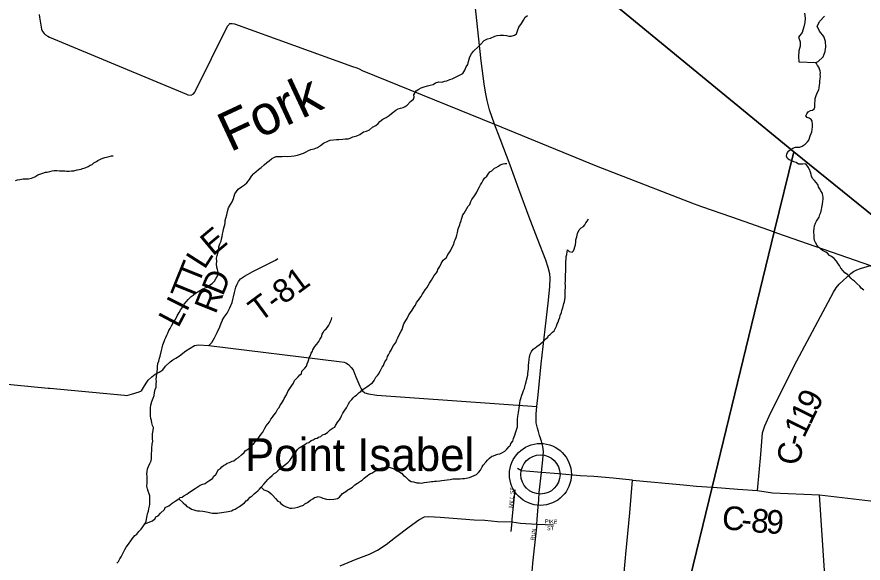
# Model space of a CAD drawing. Extents: x 1310247 to 1664935, y 235267 to 584339.
# Drawn here: x 1497464 to 1508215, y 329459 to 336394 of the extents above; entities that cross this region are included whole.
import ezdxf

# ---------------------------------------------------------------- set-up
doc = ezdxf.new("R2010")
doc.units = 0
for name, color, linetype in [('GM_X_County_Road', 7, 'Continuous'), ('GM_X_County_Road_Text', 7, 'Continuous'), ('GM_X_Minor_Lake', 7, 'Continuous'), ('GM_X_Minor_River', 7, 'Continuous'), ('GM_X_Minor_River_Text', 7, 'Continuous'), ('GM_X_State_Route', 7, 'Continuous'), ('GM_X_Township', 7, 'Continuous'), ('GM_X_Township_Road', 7, 'Continuous'), ('GM_X_Township_Road_Text', 7, 'Continuous'), ('GM_X_Township_ROW', 7, 'Continuous'), ('GM_X_Township_Subdivision', 7, 'Continuous'), ('GM_X_Township_Subdivision_Text', 7, 'Continuous'), ('GM_X_Unincorporated', 7, 'Continuous'), ('GM_X_Unincorporated_Location', 7, 'Continuous'), ('GM_X_Unincorporated_Text', 7, 'Continuous')]:
    doc.layers.add(name, color=color, linetype=linetype)

msp = doc.modelspace()

# ---------------------------------------------------------------- linework, layer by layer
at = {"layer": 'GM_X_County_Road'}
for points in [[(1506874, 330380), (1506915, 330836), (1506931, 331059), (1506937, 331113), (1506950, 331153), (1506966, 331203), (1507040, 331363), (1507375, 332029), (1507838, 332899), (1507873, 332955), (1507912, 332999), (1508061, 333136), (1508091, 333160), (1508134, 333183), (1508184, 333201), (1508308, 333237)], [(1497863, 331681), (1497884, 331679), (1498831, 331590), (1498861, 331589), (1498918, 331604), (1499019, 331633), (1499045, 331647), (1499074, 331690), (1499106, 331745), (1499133, 331781), (1499180, 331826), (1499221, 331857), (1499271, 331882), (1499294, 331897), (1499316, 331911), (1499353, 331958), (1499409, 332013), (1499444, 332040), (1499484, 332063), (1499529, 332092), (1499611, 332154), (1499720, 332221), (1499773, 332232), (1499902, 332221), (1501558, 332017), (1501620, 332010), (1501644, 332003), (1501676, 331980), (1501709, 331943), (1501734, 331911), (1501762, 331846), (1501766, 331837)], [(1506310, 330422), (1506622, 330398), (1506874, 330380), (1507062, 330352), (1507660, 330327), (1508525, 330224), (1508611, 330218), (1508671, 330227), (1508722, 330257), (1508766, 330296), (1508807, 330348), (1508927, 330527), (1509888, 331954), (1509935, 332016), (1509965, 332043), (1509999, 332057), (1510060, 332056), (1510186, 332039), (1510688, 331967), (1510706, 331965)], [(1501766, 331837), (1501770, 331826), (1501794, 331763), (1501819, 331704), (1501836, 331673), (1501855, 331645), (1501885, 331622), (1501930, 331607), (1502036, 331590), (1504071, 331446)], [(1497210, 331743), (1497863, 331681)], [(1505285, 330514), (1505934, 330451), (1506099, 330437), (1506297, 330423), (1506310, 330422)], [(1508425, 324502), (1508196, 324828), (1508120, 324927), (1508065, 325019), (1508047, 325076), (1508014, 325188), (1507987, 325289), (1507959, 325402), (1507847, 325823), (1507823, 325940), (1507813, 326025), (1507811, 326169), (1507819, 326315), (1507833, 326564), (1507841, 326866), (1507838, 327042), (1507841, 327152), (1507849, 327306), (1507850, 327552), (1507836, 327784), (1507790, 328404), (1507660, 330327)]]:
    msp.add_lwpolyline(points, dxfattribs=at)
at = {"layer": 'GM_X_Minor_Lake'}
for points in [[(1507472, 336443), (1507477, 336377), (1507476, 336325), (1507463, 336267), (1507442, 336197), (1507393, 336139), (1507416, 336077), (1507415, 336021), (1507400, 335965), (1507393, 335892), (1507399, 335826)], [(1507616, 335816), (1507644, 335828), (1507709, 335887), (1507733, 335957), (1507740, 336013), (1507737, 336083), (1507716, 336146), (1507659, 336215), (1507630, 336276), (1507665, 336342), (1507726, 336405)], [(1507399, 335826), (1507616, 335816)]]:
    msp.add_lwpolyline(points, dxfattribs=at)
at = {"layer": 'GM_X_Minor_River'}
for points in [[(1501360, 334793), (1501414, 334818), (1501446, 334828), (1501485, 334833), (1501523, 334837), (1501555, 334838), (1501605, 334843), (1501635, 334845), (1501671, 334848), (1501697, 334856), (1501733, 334871), (1501784, 334884), (1501820, 334902), (1501869, 334935), (1501905, 334943), (1501943, 334960), (1501982, 334993), (1502022, 335017), (1502052, 335040), (1502073, 335068), (1502113, 335098), (1502154, 335119), (1502194, 335144), (1502225, 335170), (1502277, 335209), (1502308, 335227), (1502336, 335236), (1502370, 335246), (1502396, 335257), (1502423, 335275), (1502463, 335320), (1502504, 335348), (1502512, 335376), (1502509, 335406), (1502536, 335454), (1502570, 335477), (1502602, 335493), (1502639, 335508), (1502679, 335519), (1502715, 335529), (1502751, 335538), (1502784, 335556), (1502824, 335569), (1502862, 335568), (1502900, 335578), (1502928, 335585), (1502963, 335601), (1502993, 335608), (1503061, 335641), (1503088, 335655), (1503130, 335678), (1503153, 335720), (1503173, 335762), (1503192, 335790), (1503203, 335830), (1503211, 335860), (1503218, 335886), (1503240, 335925), (1503265, 335959), (1503328, 336020), (1503352, 336046), (1503401, 336093), (1503444, 336118), (1503480, 336126), (1503534, 336149), (1503564, 336157), (1503602, 336164), (1503646, 336161), (1503684, 336157), (1503712, 336148), (1503742, 336148), (1503785, 336161), (1503813, 336178), (1503822, 336218), (1503842, 336264), (1503873, 336312), (1503900, 336354), (1503921, 336391), (1503949, 336413)], [(1507789, 333367), (1507764, 333396), (1507742, 333408), (1507698, 333429), (1507673, 333448), (1507651, 333466), (1507633, 333491), (1507612, 333531), (1507597, 333556), (1507593, 333584), (1507592, 333622), (1507589, 333656), (1507589, 333680), (1507592, 333708), (1507599, 333742), (1507611, 333776), (1507622, 333802), (1507641, 333825), (1507655, 333851), (1507666, 333885), (1507676, 333911), (1507687, 333947), (1507692, 333975), (1507699, 334015), (1507703, 334053), (1507706, 334081), (1507706, 334103), (1507703, 334127), (1507697, 334153), (1507678, 334188), (1507663, 334214), (1507649, 334236), (1507638, 334265), (1507597, 334318), (1507571, 334344), (1507560, 334371), (1507556, 334393), (1507545, 334425), (1507532, 334458), (1507518, 334488), (1507489, 334527), (1507451, 334525), (1507427, 334524), (1507393, 334525), (1507363, 334545), (1507336, 334556), (1507300, 334571), (1507274, 334581), (1507253, 334598), (1507243, 334626), (1507246, 334650), (1507256, 334672), (1507273, 334696), (1507295, 334709), (1507323, 334729), (1507356, 334740), (1507388, 334739), (1507410, 334741), (1507442, 334752), (1507478, 334778), (1507507, 334807), (1507526, 334829), (1507534, 334853), (1507543, 334883), (1507553, 334912), (1507562, 334934), (1507566, 334962), (1507573, 335002), (1507570, 335030), (1507569, 335069), (1507557, 335091), (1507531, 335107), (1507506, 335116), (1507488, 335140), (1507499, 335162), (1507519, 335190), (1507547, 335205), (1507570, 335211), (1507594, 335229), (1507600, 335250), (1507603, 335274), (1507602, 335301), (1507604, 335335), (1507607, 335357), (1507613, 335385), (1507632, 335430), (1507651, 335470), (1507658, 335494), (1507662, 335526), (1507667, 335552), (1507667, 335578), (1507670, 335614), (1507673, 335636), (1507671, 335664), (1507672, 335686), (1507668, 335708), (1507663, 335733), (1507653, 335755), (1507636, 335779), (1507622, 335804), (1507616, 335816)], [(1499241, 331861), (1499246, 331891), (1499252, 331923), (1499251, 331957), (1499255, 331993), (1499268, 332025), (1499276, 332061), (1499285, 332087), (1499302, 332159), (1499309, 332191), (1499319, 332229), (1499334, 332271), (1499344, 332297), (1499355, 332325), (1499367, 332353), (1499380, 332379), (1499396, 332412), (1499411, 332438), (1499429, 332472), (1499454, 332520), (1499479, 332554), (1499500, 332599), (1499526, 332643), (1499547, 332679), (1499570, 332711), (1499590, 332748), (1499617, 332780), (1499639, 332808), (1499676, 332845), (1499704, 332863), (1499733, 332888), (1499775, 332914), (1499819, 332937), (1499848, 332949), (1499878, 332962), (1499910, 332988), (1499945, 333009), (1499973, 333041), (1499994, 333075), (1500017, 333112), (1500021, 333154), (1500012, 333187), (1500006, 333215), (1500001, 333255), (1500002, 333295), (1500000, 333329), (1500007, 333365), (1500020, 333409), (1500028, 333443), (1500031, 333473), (1500043, 333511), (1500060, 333547), (1500064, 333575), (1500071, 333605), (1500075, 333637), (1500084, 333669), (1500090, 333699), (1500099, 333727), (1500105, 333755), (1500108, 333785), (1500110, 333811), (1500117, 333837), (1500132, 333883), (1500140, 333925), (1500153, 333969), (1500176, 334011), (1500200, 334046), (1500217, 334088), (1500234, 334148), (1500253, 334176), (1500275, 334206), (1500316, 334235), (1500354, 334264), (1500387, 334288), (1500417, 334330), (1500444, 334371), (1500475, 334405), (1500505, 334432), (1500533, 334456), (1500566, 334484), (1500605, 334517), (1500639, 334547), (1500669, 334568), (1500698, 334594), (1500728, 334611), (1500756, 334621), (1500798, 334620), (1500832, 334622), (1500869, 334625), (1500905, 334624), (1500947, 334628), (1500985, 334631), (1501029, 334638), (1501103, 334663), (1501140, 334683), (1501170, 334700), (1501200, 334712), (1501240, 334721), (1501285, 334738), (1501319, 334760), (1501360, 334793)], [(1497447, 334318), (1497471, 334326), (1497501, 334331), (1497545, 334338), (1497576, 334338), (1497612, 334339), (1497648, 334345), (1497691, 334364), (1497729, 334388), (1497768, 334401), (1497792, 334411), (1497828, 334422), (1497850, 334424), (1497881, 334433), (1497911, 334439), (1497939, 334444), (1497971, 334444), (1498005, 334441), (1498026, 334441), (1498052, 334438), (1498072, 334438), (1498096, 334436), (1498126, 334437), (1498156, 334441), (1498188, 334442), (1498229, 334451), (1498255, 334457), (1498279, 334463), (1498299, 334468), (1498330, 334478), (1498368, 334493), (1498393, 334511), (1498419, 334520), (1498441, 334542), (1498474, 334558), (1498494, 334571), (1498527, 334589), (1498555, 334599), (1498583, 334610), (1498604, 334614), (1498636, 334623), (1498664, 334629), (1498688, 334630)], [(1502105, 331947), (1502123, 331969), (1502132, 331993), (1502138, 332013), (1502163, 332049), (1502174, 332081), (1502184, 332104), (1502201, 332138), (1502217, 332162), (1502246, 332218), (1502265, 332242), (1502279, 332262), (1502290, 332294), (1502302, 332318), (1502325, 332367), (1502348, 332405), (1502357, 332427), (1502372, 332473), (1502380, 332497), (1502407, 332539), (1502424, 332565), (1502442, 332613), (1502465, 332642), (1502484, 332672), (1502513, 332714), (1502527, 332736), (1502542, 332768), (1502566, 332799), (1502583, 332825), (1502599, 332845), (1502612, 332871), (1502628, 332895), (1502649, 332927), (1502670, 332956), (1502688, 332984), (1502705, 333014), (1502730, 333052), (1502750, 333080), (1502767, 333111), (1502794, 333145), (1502806, 333167), (1502811, 333187), (1502837, 333225), (1502854, 333263), (1502881, 333304), (1502920, 333340), (1502939, 333376), (1502957, 333398), (1502974, 333423), (1502984, 333455), (1503013, 333507), (1503024, 333545), (1503034, 333565), (1503043, 333593), (1503052, 333623), (1503060, 333655), (1503071, 333703), (1503078, 333723), (1503092, 333755), (1503097, 333777), (1503107, 333803), (1503114, 333827), (1503120, 333851), (1503131, 333881), (1503145, 333901), (1503162, 333931), (1503180, 333963), (1503199, 333992), (1503217, 334012), (1503232, 334050), (1503243, 334076), (1503278, 334122), (1503294, 334148), (1503307, 334171), (1503323, 334207), (1503340, 334237), (1503355, 334261), (1503369, 334287), (1503384, 334315), (1503406, 334349), (1503433, 334372), (1503452, 334398), (1503474, 334426), (1503497, 334442), (1503531, 334475), (1503554, 334483), (1503582, 334498), (1503602, 334516), (1503641, 334530), (1503663, 334535), (1503687, 334535)], [(1503550, 330833), (1503576, 330841), (1503598, 330848), (1503633, 330864), (1503663, 330879), (1503688, 330905), (1503717, 330939), (1503735, 330958), (1503740, 330978), (1503764, 331006), (1503775, 331040), (1503792, 331084), (1503800, 331112), (1503822, 331188), (1503824, 331212), (1503825, 331286), (1503828, 331321), (1503837, 331373), (1503840, 331401), (1503844, 331427), (1503853, 331489), (1503860, 331525), (1503868, 331547), (1503881, 331591), (1503886, 331613), (1503902, 331651), (1503913, 331675), (1503919, 331699), (1503926, 331731), (1503935, 331761), (1503939, 331783), (1503954, 331847), (1503957, 331867), (1503962, 331925), (1503964, 331955), (1503965, 331976), (1503967, 331996), (1503974, 332050), (1503976, 332072), (1503985, 332110), (1504000, 332144), (1504022, 332176), (1504047, 332193), (1504069, 332209), (1504100, 332230), (1504122, 332246), (1504151, 332274), (1504186, 332305), (1504210, 332327), (1504218, 332347), (1504241, 332363), (1504267, 332390), (1504288, 332410), (1504302, 332432), (1504319, 332468), (1504330, 332496), (1504342, 332520), (1504351, 332550), (1504361, 332578), (1504364, 332602), (1504383, 332640), (1504387, 332666), (1504400, 332702), (1504411, 332756), (1504421, 332778), (1504426, 332806), (1504428, 332828), (1504431, 332894), (1504433, 332984), (1504431, 333015), (1504432, 333035), (1504435, 333085), (1504435, 333113), (1504438, 333173), (1504437, 333201), (1504438, 333242), (1504440, 333276), (1504441, 333332), (1504444, 333352), (1504450, 333376), (1504457, 333410), (1504459, 333436), (1504481, 333414), (1504517, 333409), (1504537, 333425), (1504544, 333445), (1504552, 333473), (1504559, 333501), (1504564, 333537), (1504566, 333563), (1504577, 333601), (1504583, 333623), (1504588, 333643), (1504606, 333691), (1504635, 333717), (1504662, 333734), (1504678, 333754), (1504694, 333778), (1504711, 333800), (1504726, 333830)], [(1508224, 332923), (1508190, 332949), (1508173, 332974), (1508134, 333009), (1508106, 333041), (1508081, 333058), (1508059, 333079), (1508040, 333103), (1508016, 333122), (1507982, 333146), (1507961, 333171), (1507934, 333206), (1507916, 333238), (1507897, 333260), (1507877, 333295), (1507848, 333326), (1507815, 333354), (1507789, 333367)], [(1501427, 332479), (1501438, 332505), (1501450, 332525), (1501459, 332551), (1501465, 332579)], [(1499091, 329959), (1499185, 329997), (1499220, 330027), (1499229, 330047), (1499257, 330060), (1499288, 330092), (1499339, 330139), (1499349, 330165), (1499394, 330187), (1499437, 330220), (1499475, 330245), (1499520, 330275), (1499540, 330291), (1499563, 330298), (1499585, 330312), (1499622, 330335), (1499646, 330353), (1499677, 330373), (1499707, 330394), (1499730, 330408), (1499766, 330431), (1499791, 330449), (1499813, 330459), (1499855, 330470), (1499878, 330486), (1499904, 330503), (1499949, 330535), (1499965, 330563), (1499990, 330586), (1500013, 330622), (1500023, 330642), (1500050, 330658), (1500066, 330682), (1500088, 330697), (1500115, 330713), (1500137, 330729), (1500166, 330736), (1500198, 330752), (1500218, 330757), (1500251, 330783), (1500279, 330799), (1500318, 330834), (1500353, 330862), (1500363, 330883), (1500386, 330899), (1500422, 330923), (1500445, 330954), (1500473, 330976), (1500508, 331022), (1500531, 331039), (1500545, 331067), (1500568, 331097), (1500587, 331123), (1500612, 331171), (1500632, 331200), (1500651, 331226), (1500671, 331254), (1500688, 331288), (1500711, 331314), (1500727, 331338), (1500754, 331369), (1500777, 331417), (1500797, 331435), (1500810, 331463), (1500826, 331485), (1500839, 331506), (1500853, 331528), (1500858, 331548), (1500891, 331596), (1500907, 331636), (1500940, 331688), (1500957, 331715), (1500978, 331745), (1500992, 331777), (1501017, 331805), (1501039, 331823), (1501058, 331850), (1501078, 331864), (1501083, 331896), (1501124, 331936), (1501142, 331960), (1501151, 331988), (1501164, 332019), (1501174, 332043), (1501178, 332065), (1501191, 332087), (1501202, 332125), (1501220, 332149), (1501223, 332169), (1501251, 332211), (1501274, 332239), (1501299, 332274), (1501311, 332298), (1501328, 332324), (1501338, 332346), (1501341, 332366), (1501355, 332388), (1501366, 332412), (1501392, 332432), (1501409, 332453), (1501427, 332479)], [(1499520, 330275), (1499575, 330224), (1499607, 330197), (1499623, 330177), (1499653, 330164), (1499683, 330145), (1499713, 330137), (1499739, 330126), (1499759, 330122), (1499785, 330122), (1499825, 330117), (1499853, 330112), (1499895, 330104), (1499927, 330099), (1499951, 330095), (1499987, 330094), (1500013, 330094), (1500033, 330097), (1500068, 330101), (1500094, 330104), (1500122, 330108), (1500148, 330113), (1500168, 330119), (1500189, 330123), (1500211, 330136), (1500237, 330142), (1500274, 330167), (1500294, 330177), (1500327, 330205), (1500357, 330226), (1500378, 330250), (1500398, 330262), (1500427, 330294), (1500453, 330311), (1500480, 330339), (1500502, 330359), (1500523, 330376), (1500547, 330396), (1500568, 330422), (1500601, 330461), (1500632, 330495), (1500654, 330521), (1500673, 330543), (1500705, 330572), (1500734, 330598), (1500756, 330611), (1500803, 330657), (1500828, 330679), (1500879, 330714), (1500909, 330741), (1500930, 330761), (1500950, 330789), (1500971, 330821), (1500988, 330853), (1501012, 330876), (1501029, 330902), (1501051, 330922), (1501092, 330949), (1501122, 330963), (1501145, 330983), (1501171, 330992), (1501202, 331016), (1501226, 331023), (1501252, 331039), (1501277, 331047), (1501297, 331058), (1501325, 331068), (1501348, 331088), (1501376, 331097), (1501409, 331119), (1501443, 331150), (1501482, 331176), (1501502, 331186), (1501513, 331206), (1501542, 331251), (1501562, 331277), (1501575, 331301), (1501589, 331327), (1501606, 331361), (1501629, 331400), (1501651, 331432), (1501676, 331480), (1501695, 331510), (1501718, 331536), (1501738, 331557), (1501759, 331577), (1501779, 331591), (1501814, 331626), (1501834, 331640), (1501852, 331660), (1501873, 331670), (1501911, 331699), (1501940, 331719), (1501960, 331736), (1501983, 331750), (1502001, 331776), (1502024, 331820), (1502047, 331840), (1502057, 331859), (1502078, 331895), (1502105, 331947)], [(1498732, 329456), (1498753, 329481), (1498773, 329511), (1498790, 329537), (1498806, 329573), (1498823, 329605), (1498833, 329631), (1498850, 329660), (1498881, 329700), (1498911, 329742), (1498928, 329769), (1498963, 329809), (1498989, 329827), (1499013, 329862), (1499042, 329888), (1499062, 329920), (1499091, 329959), (1499108, 329989), (1499112, 330017), (1499117, 330057), (1499125, 330085), (1499134, 330119), (1499140, 330147), (1499147, 330183), (1499151, 330209), (1499153, 330314), (1499146, 330340), (1499130, 330374), (1499123, 330400), (1499115, 330435), (1499118, 330477), (1499120, 330505), (1499119, 330531), (1499117, 330559), (1499114, 330593), (1499118, 330623), (1499125, 330657), (1499135, 330685), (1499154, 330725), (1499169, 330759), (1499175, 330789), (1499174, 330817), (1499174, 330843), (1499177, 330891), (1499179, 330919), (1499184, 330971), (1499189, 331007), (1499187, 331037), (1499186, 331063), (1499186, 331102), (1499193, 331144), (1499198, 331180), (1499188, 331208), (1499179, 331242), (1499173, 331270), (1499166, 331297), (1499162, 331327), (1499163, 331355), (1499161, 331389), (1499160, 331429), (1499166, 331463), (1499179, 331509), (1499196, 331555), (1499208, 331587), (1499213, 331625), (1499220, 331665), (1499232, 331695), (1499233, 331735), (1499237, 331765), (1499232, 331791), (1499237, 331829), (1499241, 331861)], [(1500568, 330422), (1500601, 330389), (1500627, 330381), (1500661, 330366), (1500695, 330339), (1500715, 330319), (1500748, 330280), (1500778, 330247), (1500800, 330235), (1500819, 330214), (1500849, 330190), (1500883, 330175), (1500911, 330163), (1500933, 330156), (1500957, 330156), (1500995, 330159), (1501034, 330169), (1501068, 330180), (1501104, 330193), (1501123, 330213), (1501155, 330229), (1501192, 330260), (1501223, 330276), (1501245, 330292), (1501265, 330297), (1501293, 330305), (1501319, 330296), (1501349, 330282), (1501397, 330269), (1501439, 330268), (1501492, 330271), (1501514, 330277), (1501536, 330281), (1501561, 330296), (1501602, 330342), (1501644, 330367), (1501667, 330389), (1501687, 330399), (1501726, 330422), (1501758, 330454), (1501791, 330473), (1501828, 330501), (1501852, 330512), (1501876, 330538), (1501913, 330568), (1501934, 330585), (1501956, 330595), (1501982, 330607), (1502003, 330624), (1502023, 330630), (1502051, 330650), (1502104, 330669), (1502132, 330672), (1502152, 330676), (1502194, 330675), (1502218, 330669), (1502244, 330658), (1502274, 330644), (1502296, 330631), (1502328, 330613), (1502352, 330600), (1502375, 330570), (1502395, 330559), (1502421, 330531), (1502441, 330516), (1502473, 330496), (1502501, 330489), (1502547, 330478), (1502577, 330476), (1502609, 330475), (1502639, 330481), (1502673, 330488), (1502706, 330490), (1502730, 330497), (1502750, 330497), (1502770, 330499), (1502794, 330500), (1502837, 330503), (1502861, 330509), (1502897, 330512), (1502931, 330516), (1502970, 330521), (1503004, 330527), (1503042, 330528), (1503094, 330527), (1503126, 330531), (1503151, 330534), (1503213, 330545), (1503243, 330557), (1503272, 330570), (1503302, 330586), (1503329, 330610), (1503356, 330641), (1503376, 330681), (1503389, 330703), (1503420, 330739), (1503444, 330768), (1503469, 330790), (1503497, 330816), (1503518, 330821), (1503550, 330833)]]:
    msp.add_lwpolyline(points, dxfattribs=at)
at = {"layer": 'GM_X_State_Route'}
for points in [[(1504121, 331030), (1504121, 331031), (1504105, 331080), (1504090, 331130), (1504078, 331171), (1504063, 331241), (1504061, 331353), (1504071, 331446), (1504086, 331597), (1504126, 331990), (1504175, 332429), (1504216, 332796), (1504236, 332971), (1504239, 333079), (1504234, 333132), (1504215, 333213), (1504184, 333306), (1504079, 333577), (1503973, 333850), (1503839, 334207), (1503729, 334511), (1503603, 334848), (1503533, 335034), (1503470, 335213), (1503438, 335334), (1503417, 335437), (1503400, 335545), (1503364, 335835), (1503330, 336149), (1503287, 336547)], [(1505165, 329201), (1505199, 329571), (1505251, 330098), (1505285, 330514), (1505157, 330526), (1505038, 330536), (1504795, 330559), (1504619, 330569), (1504347, 330591), (1504128, 330610), (1504144, 330770), (1504153, 330876), (1504147, 330941), (1504134, 330990), (1504130, 331009), (1504121, 331030)], [(1501570, 329422), (1501775, 329507), (1501942, 329574), (1502047, 329623), (1502155, 329695), (1502274, 329787), (1502448, 329921), (1502571, 330010), (1502643, 330046), (1502699, 330051), (1502841, 330042), (1502952, 330035), (1503274, 330010), (1503410, 330004), (1503572, 329988), (1503750, 329983), (1503863, 329966), (1504069, 329954), (1504074, 330014), (1504083, 330121), (1504093, 330261), (1504101, 330356), (1504128, 330610)]]:
    msp.add_lwpolyline(points, dxfattribs=at)
at = {"layer": 'GM_X_Township'}
for points in [[(1533276, 348457), (1532824, 344490), (1532312, 340083), (1532006, 337422), (1531505, 333071), (1531469, 332747), (1531158, 329654), (1530772, 326029), (1528532, 326348), (1524346, 326932), (1524319, 326936), (1516670, 327973), (1515410, 328144), (1515396, 328155), (1510688, 331967), (1508770, 333520), (1507334, 334683), (1504210, 337249), (1502439, 338703), (1501850, 339181), (1500490, 340284), (1499584, 342445), (1499395, 345650), (1499188, 348671)], [(1494192, 337958), (1499473, 342306), (1499584, 342445), (1500490, 340284), (1501850, 339181), (1502439, 338703), (1504210, 337249), (1507334, 334683), (1507086, 333664), (1506297, 330423), (1505134, 325645), (1504652, 323631), (1504598, 323405), (1504587, 323349), (1504578, 323300), (1503185, 317642)], [(1503185, 317642), (1504578, 323300), (1504587, 323349), (1504598, 323405), (1504652, 323631), (1505134, 325645), (1506297, 330423), (1507086, 333664), (1507334, 334683), (1508770, 333520), (1510688, 331967), (1515396, 328155), (1515410, 328144), (1516670, 327973), (1524319, 326936), (1524346, 326932), (1528532, 326348), (1530772, 326029), (1530509, 323916), (1530186, 322432), (1530006, 319686), (1529806, 317987)]]:
    msp.add_lwpolyline(points, dxfattribs=at)
at = {"layer": 'GM_X_Township_Road'}
for points in [[(1497746, 336427), (1497753, 336392), (1497772, 336266), (1497777, 336241), (1497788, 336211), (1497811, 336182), (1497827, 336166), (1497855, 336151), (1497878, 336138), (1497927, 336118), (1497928, 336118)], [(1498713, 335790), (1498714, 335790), (1499618, 335413), (1499636, 335407), (1499678, 335402), (1499706, 335417), (1499724, 335437), (1499735, 335456), (1500141, 336276), (1500156, 336296), (1500162, 336303)], [(1500162, 336303), (1500163, 336305), (1500170, 336313), (1500200, 336313), (1500230, 336306), (1501729, 335764), (1501782, 335746), (1501820, 335729), (1501849, 335716), (1503533, 335034)], [(1497928, 336118), (1498713, 335790)], [(1503533, 335034), (1504825, 334502), (1506067, 334020), (1506161, 333987)], [(1506161, 333987), (1506162, 333987), (1506543, 333854)], [(1500497, 333180), (1500545, 333203), (1500717, 333287), (1500750, 333306), (1500780, 333328)], [(1499902, 332221), (1499939, 332262), (1499976, 332318), (1500008, 332385), (1500040, 332460), (1500058, 332506), (1500075, 332542), (1500077, 332546), (1500098, 332583), (1500137, 332632), (1500171, 332700), (1500197, 332767), (1500230, 332895), (1500246, 332962), (1500261, 333002), (1500278, 333034), (1500305, 333067), (1500354, 333104), (1500460, 333161), (1500497, 333180)]]:
    msp.add_lwpolyline(points, dxfattribs=at)
at = {"layer": 'GM_X_Township_ROW'}
for points in [[(1506543, 333854), (1506543, 333854), (1507086, 333664), (1507115, 333654)], [(1507115, 333654), (1507116, 333654), (1508308, 333237), (1508458, 333124), (1508636, 332957), (1508853, 332745), (1508873, 332721)]]:
    msp.add_lwpolyline(points, dxfattribs=at)
at = {"layer": 'GM_X_Township_Subdivision'}
for points in [[(1504128, 330610), (1503979, 330624), (1503874, 330629), (1503824, 330658)], [(1503789, 330390), (1503753, 330015), (1503750, 329983)], [(1503750, 329983), (1503739, 329860)], [(1504069, 329954), (1504015, 329459)], [(1504069, 329954), (1504282, 329944)], [(1504015, 329459), (1504014, 329453), (1503959, 328794), (1503958, 328739), (1503964, 328677), (1503967, 328633)]]:
    msp.add_lwpolyline(points, dxfattribs=at)
at = {"layer": 'GM_X_Unincorporated'}
for radius in [393, 249]:
    msp.add_circle((1504115, 330585), radius, dxfattribs=at)
at = {"layer": 'GM_X_Unincorporated_Location'}
msp.add_line((1504115, 330585), (1504115, 330585), dxfattribs=at)

# ---------------------------------------------------------------- texts
at = {"layer": 'GM_X_County_Road_Text'}
for s, rotation, p in [('9', 63.7247, (1507627, 331368)), ('1', 63.7305, (1507545, 331202)), ('1', 63.7596, (1507464, 331036)), ('-', 77.1859, (1507443, 330934)), ('C', 85.2015, (1507424, 330699)), ('C', 354.1391, (1506411, 329894)), ('8', 354.8626, (1506783, 329856)), ('9', 356.4322, (1506976, 329839)), ('-', 354.3059, (1506657, 329869))]:
    msp.add_text(s, height=300, rotation=rotation, dxfattribs=at).set_placement(p)
at = {"layer": 'GM_X_Minor_River_Text'}
msp.add_text('Fork', height=500, rotation=25.0101, dxfattribs=at).set_placement((1500173, 334673))
at = {"layer": 'GM_X_Township_Road_Text'}
for s, rotation, p in [('E', 39.8429, (1499953, 333349)), ('L', 57.4618, (1499848, 333178)), ('T', 68.1309, (1499771, 332983)), ('D', 67.6074, (1500079, 332839)), ('T-81', 36.3858, (1500548, 332511)), ('T', 68.1398, (1499687, 332774)), ('R', 68.1942, (1499988, 332611)), ('I', 63.4079, (1499621, 332640)), ('L', 62.1143, (1499513, 332435))]:
    msp.add_text(s, height=300, rotation=rotation, dxfattribs=at).set_placement(p)
at = {"layer": 'GM_X_Township_Subdivision_Text'}
for s, rotation, p in [('MILL ST', 84.7129, (1503762, 330158)), ('PIKE', 358.1498, (1504172, 329964)), ('RUN', 82.1508, (1504039, 329745)), ('ST', 356.4186, (1504198, 329878))]:
    msp.add_text(s, height=50, rotation=rotation, dxfattribs=at).set_placement(p)
at = {"layer": 'GM_X_Unincorporated_Text'}
msp.add_text('Point Isabel', height=417, rotation=0, dxfattribs=at).set_placement((1500361, 330628))

doc.saveas('drawing.dxf')
